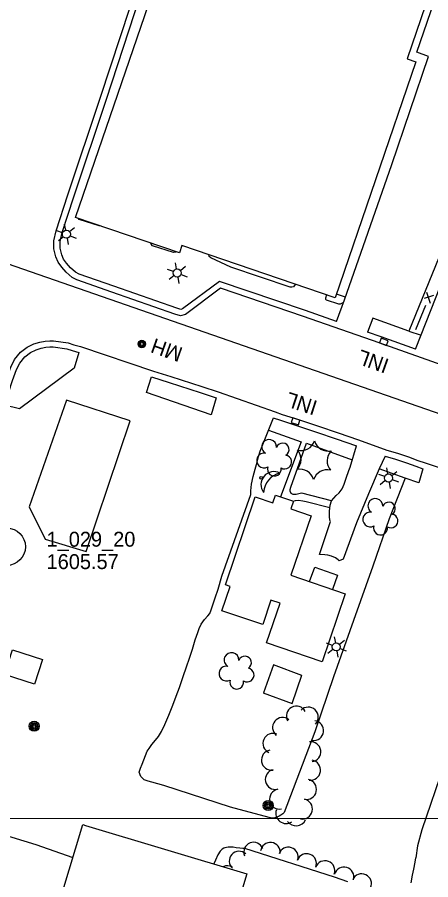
# Model space of a CAD drawing. Extents: x 189384 to 193282, y 256970 to 260388.
# Drawn here: x 190859 to 191025.2, y 258486.9 to 258833.8 of the extents above; entities that cross this region are included whole.
import ezdxf

# ---------------------------------------------------------------- set-up
doc = ezdxf.new("R2010")
doc.units = 0
for name, color, linetype in [('E_DRN_Grate', 7, 'Continuous'), ('E_DWY', 7, 'Continuous'), ('E_LAND_Vegetation', 7, 'Continuous'), ('E_MAP_GridLines', 7, 'Continuous'), ('E_MAP_Limits', 7, 'Continuous'), ('E_MAP_PassPoints', 7, 'Continuous'), ('E_MISCPROP', 7, 'Continuous'), ('E_MISCPROP_HvyLine', 7, 'Continuous'), ('E_MISCPROP_Railing', 7, 'Continuous'), ('E_MISCPROP_Solid', 7, 'Continuous'), ('E_PATH_Sidewalk', 7, 'Continuous'), ('E_RDWY', 7, 'Continuous')]:
    doc.layers.add(name, color=color, linetype=linetype)

# ---------------------------------------------------------------- blocks, each defined once
blk = doc.blocks.new('PP')
at = {"layer": 'E_MAP_PassPoints'}
for radius in [7.5, 0.96]:
    blk.add_circle((0, 0), radius, dxfattribs=at)
blk = doc.blocks.new('INLT')
at = {"layer": 'E_MISCPROP_Railing'}
blk.add_lwpolyline([(3, -2), (3, 0), (0, 0), (0, -2), (3, -2)], dxfattribs=at)
blk = doc.blocks.new('INL_5')
at = {"layer": 'E_MISCPROP_Railing'}
blk.add_text('INL', height=6, rotation=360, dxfattribs=at).set_placement((-5.79, -2.75))
blk = doc.blocks.new('LTP')
at = {"layer": 'E_MISCPROP'}
for p, q in [((-0.78, 1.46), (-1.98, 3.76)), ((0.86, 1.37), (2.22, 3.6)), ((-1.61, 0.09), (-4.22, 0.17)), ((1.66, 0), (4.18, -0.06)), ((-0.86, -1.4), (-2.22, -3.59)), ((0.78, -1.44), (2.02, -3.62))]:
    blk.add_line(p, q, dxfattribs=at)
blk.add_circle((0.02, 0.01), 1.64, dxfattribs=at)
blk = doc.blocks.new('MHO_8')
at = {"layer": 'E_DRN_Grate'}
for centre, radius in [((0.04, -0.06), 1.5), ((0.04, -0.06), 1.22), ((0.04, -0.07), 0.968), ((0.01, -0.08), 0.605)]:
    blk.add_circle(centre, radius, dxfattribs=at)
blk = doc.blocks.new('INLT_5')
at = {"layer": 'E_MISCPROP_Railing'}
blk.add_lwpolyline([(3, -2), (3, 0), (0, 0), (0, -2), (3, -2)], dxfattribs=at)
blk = doc.blocks.new('LTP_14')
at = {"layer": 'E_MISCPROP'}
for p, q in [((-0.8, 1.43), (-2, 3.73)), ((0.9, 1.42), (2.27, 3.65)), ((-1.63, 0.07), (-4.24, 0.14)), ((-0.88, -1.42), (-2.24, -3.61)), ((0.76, -1.47), (2, -3.65)), ((1.64, -0.02), (4.16, -0.09))]:
    blk.add_line(p, q, dxfattribs=at)
blk.add_circle((0, 0), 1.64, dxfattribs=at)
blk = doc.blocks.new('POLE_15')
at = {"layer": 'E_MISCPROP'}
for centre, radius in [((-0.01, 0.02), 2.02), ((-0.01, 0.03), 1.52), ((0, -0.01), 1.01), ((0, 0), 0.502)]:
    blk.add_circle(centre, radius, dxfattribs=at)
blk = doc.blocks.new('POLE_16')
at = {"layer": 'E_MISCPROP'}
for centre, radius in [((-0.01, 0.02), 2.02), ((-0.01, 0.03), 1.52), ((0, -0.01), 1.01), ((0, 0), 0.502)]:
    blk.add_circle(centre, radius, dxfattribs=at)
blk = doc.blocks.new('SDSH')
at = {"layer": 'E_MISCPROP_Solid'}
blk.add_circle((0.03, 0.01), 0.562, dxfattribs=at)
for centre, radius, start, end in [((-11.02, 2.94), 8.55, 302.6556, 15.6397), ((-5.68, 0.91), 5.22, 262, 56.2984)]:
    blk.add_arc(centre, radius, start, end, dxfattribs=at)
blk = doc.blocks.new('TREE_14')
at = {"layer": 'E_LAND_Vegetation'}
for centre, radius, start, end in [((-1.47, 4.28), 2.78, 1.3948, 209.1678), ((3.57, 2.42), 2.97, 278.4239, 139.6578), ((-4.47, 0.2), 2.78, 78.0718, 279.0828), ((-2.01, -4.2), 2.61, 140.7799, 358.7125), ((3.46, -3.43), 2.97, 196.0747, 79.048)]:
    blk.add_arc(centre, radius, start, end, dxfattribs=at)
blk = doc.blocks.new('PINEL_6')
at = {"layer": 'E_LAND_Vegetation'}
for centre, start, end in [((-8.14, 7.32), 275.2115, 0.9764), ((2.26, 10.71), 215.2115, 300.9764), ((10.41, 3.41), 155.2115, 240.9765), ((-10.4, -3.39), 335.2115, 60.9764), ((8.15, -7.3), 95.2115, 180.9765), ((-2.25, -10.7), 35.2115, 120.9765)]:
    blk.add_arc(centre, 5.72, start, end, dxfattribs=at)

msp = doc.modelspace()

# ---------------------------------------------------------------- linework, layer by layer
at = {"layer": 'E_DWY'}
for points in [[(190987.34, 258711.46), (190990.55, 258720.18), (191009.54, 258774.56), (191024.26, 258818.08), (191019.52, 258819.7), (191032.25, 258856.88), (190988.11, 258872.34), (190995.24, 258889.19)], [(191083.43, 258859.69), (191081.31, 258858.31), (191079.09, 258856.15), (191076.66, 258852.58), (191074.8, 258849.66), (191072.27, 258842.23), (191055.83, 258802.27), (191040.5, 258766.67), (191016.39, 258707.62), (191001.84, 258712.79), (190999.73, 258707.14)], [(191019.08, 258700.29), (191025.32, 258716.33), (191037.25, 258746.63), (191044.06, 258760.64), (191049.42, 258770.03), (191054.06, 258775.87), (191059.44, 258783.95), (191069.67, 258801.24), (191077.54, 258816.85), (191080.74, 258824)], [(190883.68, 258698.97), (190881.79, 258692.63), (190859.9, 258676.29), (190853.88, 258677.79)], [(190938.95, 258680.76), (190936.89, 258673.88), (190936.89, 258673.88), (190910.99, 258682.83), (190912.99, 258689.13)], [(190909.13, 258533.48), (190911.22, 258538.66), (190911.93, 258539.67), (190913.06, 258541.28), (190914.49, 258543), (190915.69, 258544.54), (190916.99, 258546.5), (190918.3, 258549.36), (190919.88, 258553.1), (190921.46, 258557.09), (190922.84, 258560.82), (190924.19, 258564.31), (190925.66, 258568.67), (190927.03, 258572.54), (190928.17, 258576.09), (190929.35, 258579.61), (190930.54, 258583.38), (190931.51, 258586.33), (190932.12, 258587.94), (190932.9, 258589.74), (190934.28, 258591.65), (190935.55, 258593.07), (190936.37, 258594.06), (190936.89, 258595.42), (190937.5, 258597.09), (190938.58, 258600.32), (190939.68, 258603.74), (190941.23, 258609), (190952.85, 258641.86), (190952.91, 258643.38), (190953.14, 258645.97), (190953.77, 258649.04), (190954.56, 258652.11), (190955.34, 258654.93), (190956.11, 258657.61), (190956.64, 258659.35), (190961.94, 258672.68)], [(191006.87, 258657.34), (191004.42, 258652.17), (191000.14, 258642.12), (190995.38, 258630.47), (190990.02, 258615.92), (190988.37, 258615.2), (190987.99, 258615.64), (190986.93, 258616.37), (190985.23, 258617.08), (190983.85, 258617.5), (190982.6, 258617.65), (190980.4, 258617.73), (190984.93, 258631.04), (190984.67, 258631.58), (190984.5, 258633.04), (190984.49, 258635.18), (190984.72, 258637.55), (190985.34, 258639.27), (190987.21, 258641.45), (190988.42, 258642.6), (190989.54, 258644.2), (190990.31, 258646.07), (190991.15, 258648.44), (190992.24, 258651.49), (190992.79, 258652.89), (190995.3, 258661.48)], [(191022.01, 258652.21), (191020.41, 258646.54), (191020.41, 258646.54), (191014.88, 258648.39), (191008.51, 258632.03), (191001.9, 258612.99), (190994.1, 258591.14), (190986.07, 258568.59), (190978.53, 258546.47), (190966.26, 258513.92)], [(191046.82, 258643.97), (191044.64, 258638.43), (191067.34, 258630.85), (191061.45, 258619.68), (191050.47, 258590.58), (191041.67, 258565.56), (191030.56, 258533.32), (191021.57, 258506.99), (191019.86, 258500.62), (191019.21, 258495.79)], [(190976.48, 258606.85), (190978.62, 258612.69), (190987.68, 258609.38), (190985.69, 258603.72)], [(190806.66, 258535.84), (190812.83, 258534.19), (190808.3, 258519.39), (190842.24, 258508.44), (190866.49, 258501.09), (190881.34, 258495.93)], [(190966.26, 258513.92), (190965.71, 258513.41), (190964.95, 258512.87), (190964.3, 258512.47), (190963.34, 258512.07), (190962.5, 258511.84), (190961.34, 258511.74), (190960.21, 258511.97), (190944.66, 258516.06), (190917.88, 258524.89), (190913.1, 258526.2), (190911.57, 258526.61), (190910.84, 258526.8), (190909.97, 258527.07), (190908.69, 258528.39), (190908, 258530.19), (190908.48, 258531.83), (190909.13, 258533.48)], [(190991.81, 258486.07), (190986.42, 258487.98), (190950.41, 258499.5), (190949.68, 258499.54), (190948.43, 258499.67), (190946.95, 258499.81), (190945.77, 258499.97), (190943.8, 258499.97), (190942.4, 258499.79), (190942.05, 258499.68), (190941.3, 258499.27), (190940.51, 258498.48), (190939.6, 258496.98), (190938.66, 258494.86), (190938.04, 258493.27)], [(191017.31, 258485.74), (191017.89, 258488.83), (191018.36, 258491.23), (191018.92, 258494.05), (191019.21, 258495.79)]]:
    msp.add_lwpolyline(points, dxfattribs=at)
at = {"layer": 'E_LAND_Vegetation'}
for centre, radius, start, end in [((190971.16, 258552.72), 4.03, 28.3492, 208.3339), ((190975.94, 258552.33), 4.03, 316.1079, 136.0926), ((190965.63, 258548.15), 4.03, 51.1981, 231.1828), ((190978.06, 258546.91), 4.03, 262.6216, 82.6063), ((190961.76, 258541.78), 4.03, 66.4639, 246.4486), ((190976.94, 258538.43), 4.03, 277.3495, 97.3342), ((190961.14, 258535.04), 4.03, 99.1584, 279.1431), ((190976.86, 258531), 4.03, 261.4432, 81.4279), ((190962.71, 258527.26), 4.03, 102.1722, 282.1569), ((190975.22, 258523.25), 4.03, 258.2146, 78.1992), ((190964.42, 258519.35), 4.03, 100.8815, 280.8661), ((190973.58, 258515.36), 4.03, 258.2146, 78.1992), ((190967.07, 258513.7), 4.17, 161.8707, 303.3092), ((190971.06, 258512.79), 4.17, 214.6284, 334.4425), ((190953.97, 258498.04), 3.95, 21.2111, 201.1958), ((190960.7, 258498), 3.95, 352.5979, 172.5826), ((190948.12, 258494.43), 3.95, 47.3599, 227.3446), ((190967.93, 258496.08), 3.95, 341.4378, 161.4225), ((190975.27, 258493.46), 3.95, 338.653, 158.6377), ((190982.66, 258490.62), 3.95, 339.1518, 159.1364), ((190943.48, 258488.64), 3.95, 59.8855, 116.5872), ((190990.29, 258488.09), 3.95, 343.1631, 163.1477), ((190997.39, 258485.36), 3.95, 335.4728, 155.4575)]:
    msp.add_arc(centre, radius, start, end, dxfattribs=at)
at = {"layer": 'E_MAP_GridLines'}
for p in [(189647.05, 258510.74), (190147.05, 258511.09), (190147.05, 258511.09)]:
    msp.add_line(p, (191647.04, 258512.16), dxfattribs=at)
at = {"layer": 'E_MAP_Limits'}
msp.add_lwpolyline([(190457.96, 258872.88), (191213.57, 258610.1)], dxfattribs=at)
msp.add_lwpolyline([(190457.96, 258872.88), (191213.57, 258610.1)], dxfattribs=at)
at = {"layer": 'E_MISCPROP_HvyLine'}
for points in [[(190986.8, 258721.02), (190925.17, 258742.07), (190925.17, 258742.07), (190924.12, 258739.02), (190924.12, 258739.02), (190882.45, 258753.26), (190882.45, 258753.26), (190928.81, 258888.99), (191028.56, 258854.92), (191028.56, 258854.92), (191015.65, 258817.13), (191015.65, 258817.13), (191019.21, 258815.92), (191019.21, 258815.92), (190986.8, 258721.02)], [(190886.66, 258618.96), (190904.38, 258671.46), (190878.78, 258679.8), (190863.7, 258636.93), (190870.23, 258623.92)], [(190968.92, 258609.42), (190990.8, 258601.98), (190981.48, 258574.6), (190959.21, 258582.17), (190964.63, 258598.1), (190960.96, 258599.35), (190957.62, 258589.53), (190941.22, 258595.11), (190944.55, 258604.9), (190942.64, 258605.55), (190954.66, 258640.9), (190961.69, 258638.51), (190962.74, 258641.59), (190969.95, 258639.13), (190968.91, 258636.08), (190977.04, 258633.31)], [(190869.17, 258575.55), (190865.95, 258565.58), (190853.86, 258569.48), (190857.08, 258579.45)], [(190886.36, 258508.79), (190951.2, 258489.32), (190926.44, 258406.87), (190917.07, 258409.69), (190909, 258382.8), (190883.62, 258390.42), (190891.62, 258417.08), (190860.48, 258426.43), (190885.3, 258509.11)]]:
    msp.add_lwpolyline(points, close=True, dxfattribs=at)
at = {"layer": 'E_MISCPROP_Railing'}
for p, q in [((191023.5, 258723.26), (191024.99, 258718.87)), ((191026.25, 258721.96), (191022.5, 258720.66))]:
    msp.add_line(p, q, dxfattribs=at)
msp.add_lwpolyline([(191023.08, 258717.93), (191019.05, 258708.09)], dxfattribs=at)
at = {"layer": 'E_PATH_Sidewalk'}
for points in [[(190892.08, 258749.97), (190891.88, 258749.92), (190883.92, 258752.52), (190883.64, 258752.85)], [(190922.95, 258739.42), (190922.72, 258739.31), (190921.83, 258739.25), (190913.4, 258741.91), (190912.85, 258742.48), (190912.7, 258742.92)], [(190970.7, 258726.52), (190970.64, 258726.36), (190969.95, 258725.43), (190969.4, 258725.25), (190968.66, 258725.21), (190944.85, 258733.25), (190936.77, 258737.01), (190936.12, 258737.62), (190936.01, 258738.37)], [(190983.29, 258722.22), (190982.85, 258720.87), (190982.88, 258720.36), (190983.13, 258720.14), (190988.09, 258718.51), (190988.83, 258718.56), (190990.2, 258719.22)], [(190990.93, 258721.26), (190987.3, 258722.48)], [(191016.39, 258707.62), (191021.29, 258705.98)], [(190959.96, 258667.69), (190973.04, 258663.01), (190973.04, 258663.01), (190964.77, 258640.89)], [(190985.33, 258639.26), (190973.32, 258642.34), (190972.63, 258642.32), (190971.03, 258641.83), (190969.93, 258641.81), (190969.04, 258642.31), (190968.61, 258643.14), (190968.69, 258643.91), (190968.9, 258644.83), (190975.27, 258662.51), (190993.64, 258655.79)], [(191014.88, 258648.39), (191004.42, 258652.17)], [(190969.92, 258639.14), (190970.84, 258639.5), (190972.07, 258639.63), (190973.81, 258639.37), (190975.14, 258639.05), (190984.62, 258636.58)], [(190973.4, 258569.13), (190961.94, 258573.32), (190957.9, 258562.07)], [(190957.87, 258562.08), (190969.44, 258557.86), (190973.41, 258569.15)]]:
    msp.add_lwpolyline(points, dxfattribs=at)
at = {"layer": 'E_RDWY'}
for points in [[(190987.34, 258711.46), (190974.87, 258715.81), (190940.29, 258727.57), (190925.45, 258716.54), (190924.67, 258716.31), (190923.16, 258716.78), (190897.86, 258725.66), (190883.9, 258730.47), (190882.45, 258731.25), (190880.41, 258733.08), (190878.76, 258734.86), (190877.56, 258736.48), (190876.83, 258738.23), (190876.17, 258740.9), (190876.21, 258743.61), (190876.98, 258747.2), (190881.72, 258761.6), (190894.8, 258800.81), (190910.72, 258849.44), (190922.43, 258887.43), (190925.57, 258898.31), (190927.31, 258904.33)], [(191032.02, 258693.03), (191004.43, 258702.85), (190974.06, 258713.45), (190940.73, 258724.78), (190926.58, 258714.26), (190924.65, 258713.7), (190922.37, 258714.41), (190897.04, 258723.3), (190882.9, 258728.17), (190881, 258729.19), (190878.65, 258731.3), (190876.83, 258733.26), (190875.37, 258735.24), (190874.45, 258737.44), (190873.67, 258740.61), (190873.72, 258743.89), (190874.57, 258747.86), (190879.35, 258762.38), (190892.43, 258801.6), (190908.33, 258850.2)], [(191019.08, 258700.29), (191005.26, 258705.21), (190999.73, 258707.14)], [(190851.5, 258678.55), (190854.67, 258688.49), (190856.35, 258693.13), (190857.91, 258696.12), (190860.32, 258699.09), (190862.92, 258701.08), (190865.67, 258702.43), (190868.04, 258703.16), (190870.2, 258703.56), (190872.03, 258703.69), (190873.02, 258703.7), (190873.58, 258703.71), (190879.43, 258702.88), (190881.77, 258702.12), (190884.37, 258701.37), (190913.68, 258691.53)], [(190853.88, 258677.79), (190857.04, 258687.69), (190858.64, 258692.12), (190860.01, 258694.74), (190862.08, 258697.28), (190864.24, 258698.95), (190866.6, 258700.1), (190868.64, 258700.73), (190870.52, 258701.08), (190872.13, 258701.19), (190873.05, 258701.2), (190873.41, 258701.21), (190878.86, 258700.44), (190881.04, 258699.73), (190883.68, 258698.97)], [(190912.92, 258689.15), (190919.99, 258686.89), (190932.44, 258682.86), (190938.95, 258680.76)], [(190913.68, 258691.53), (190920.76, 258689.27), (190933.21, 258685.24), (190939.71, 258683.14), (190962.7, 258675.06)], [(190962.7, 258675.06), (190965.51, 258674.09), (190971.96, 258672.01), (190980.09, 258669.32), (190987.91, 258666.65), (190996.11, 258663.84), (191007.58, 258659.74)], [(190961.88, 258672.7), (190964.72, 258671.72), (190971.18, 258669.64), (190979.3, 258666.95), (190987.1, 258664.29), (190995.3, 258661.48)], [(191006.87, 258657.34), (191011.01, 258656.12), (191015.4, 258654.61), (191019.15, 258653.25), (191022.01, 258652.21)], [(191007.58, 258659.74), (191011.77, 258658.51), (191016.23, 258656.96), (191020, 258655.6), (191022.86, 258654.57), (191047.63, 258646.33)]]:
    msp.add_lwpolyline(points, dxfattribs=at)

# ---------------------------------------------------------------- block references
at = {"layer": 'E_DRN_Grate', "xscale": 0.9999984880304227, "yscale": 0.9999984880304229, "rotation": 160.5206853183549}
msp.add_blockref('MHO_8', (190909.07, 258702.31), dxfattribs=at)
at = {"layer": 'E_LAND_Vegetation'}
for name, p, xscale, yscale, rotation in [('TREE_14', (190962.33, 258656.62), 0.9999984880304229, 0.9999984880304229, 160.52068436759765), ('PINEL_6', (190978.28, 258655.67), 0.9999984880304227, 0.9999984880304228, 160.5206840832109), ('TREE_14', (191005.01, 258632.9), 0.9999984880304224, 0.9999984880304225, 160.52068360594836), ('TREE_14', (190947.21, 258570.92), 0.9999984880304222, 0.9999984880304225, 160.52068463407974)]:
    msp.add_blockref(name, p, dxfattribs=dict(at, xscale=xscale, yscale=yscale, rotation=rotation))
at = {"layer": 'E_MAP_PassPoints', "rotation": 0.040713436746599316}
msp.add_blockref('PP', (190854.77, 258620.85), dxfattribs=at)
at = {"layer": 'E_MISCPROP'}
for p, rotation in [((190878.76, 258746.54), 161.13015877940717), ((190923.3, 258730.96), 161.13015798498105)]:
    msp.add_blockref('LTP', p, dxfattribs=dict(at, rotation=rotation))
for name, p, xscale, yscale, rotation in [('LTP_14', (191008.2, 258648.5), 0.9999984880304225, 0.9999984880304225, 160.52068354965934), ('LTP_14', (190987.18, 258580.58), 0.999998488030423, 0.9999984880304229, 160.52068392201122), ('POLE_16', (190865.78, 258548.68), 0.9999984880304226, 0.9999984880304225, 160.5206860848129), ('POLE_15', (190959.85, 258516.83), 0.9999984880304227, 0.9999984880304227, 160.52068440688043)]:
    msp.add_blockref(name, p, dxfattribs=dict(at, xscale=xscale, yscale=yscale, rotation=rotation))
at = {"layer": 'E_MISCPROP_Railing', "yscale": 1.0000021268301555}
for name, p, xscale, rotation in [('INLT', (191007.36, 258701.81), 1.0000021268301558, 160.4125870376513), ('INL_5', (191002.48, 258695.45), 1.0000021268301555, 160.41258712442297)]:
    msp.add_blockref(name, p, dxfattribs=dict(at, xscale=xscale, rotation=rotation))
at = {"layer": 'E_MISCPROP_Railing'}
for name, p, rotation in [('INL_5', (190973.71, 258678.51), 161.93540231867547), ('INLT_5', (190969.72, 258672.73), -18.06459761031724)]:
    msp.add_blockref(name, p, dxfattribs=dict(at, rotation=rotation))
at = {"layer": 'E_MISCPROP_Solid', "xscale": 0.9999984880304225, "yscale": 0.9999984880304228, "rotation": 160.52068446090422}
msp.add_blockref('SDSH', (190957.08, 258648.6), dxfattribs=at)

# ---------------------------------------------------------------- texts
at = {"layer": 'E_DRN_Grate'}
msp.add_text('MH', height=6, rotation=160.5209, dxfattribs=at).set_placement((190925.93, 258700.7))
at = {"layer": 'E_MAP_PassPoints'}
for s, p in [('1_029_20', (190870.76, 258620.86)), ('1605.57', (190870.77, 258611.86))]:
    msp.add_text(s, height=6, rotation=0.0407, dxfattribs=at).set_placement(p)

doc.saveas('drawing.dxf')
